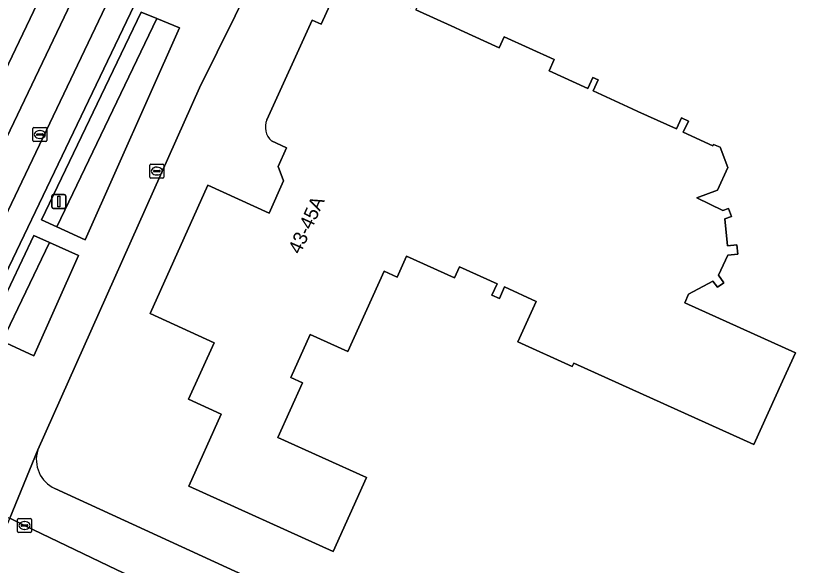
# Model space of a CAD drawing. Extents: x 161354 to 162026, y 386504 to 387460.
# Drawn here: x 161675.8 to 161732.9, y 386965.7 to 387005.2 of the extents above; entities that cross this region are included whole.
import ezdxf

# ---------------------------------------------------------------- set-up
doc = ezdxf.new("R2010")
doc.units = 0
for name, color, linetype in [('IMGEO_Brandkraan', 7, 'Continuous'), ('IMGEO_Erf', 7, 'Continuous'), ('IMGEO_Groenvoorziening', 7, 'Continuous'), ('IMGEO_Kolk', 7, 'Continuous'), ('IMGEO_Lichtmast', 7, 'Continuous'), ('IMGEO_Pand', 7, 'Continuous'), ('IMGEO_Pand_nummerreeks', 7, 'Continuous'), ('IMGEO_Parkeervlak_open', 7, 'Continuous'), ('IMGEO_Rijbaan_lokaal_open', 7, 'Continuous'), ('IMGEO_Voetpad_open', 7, 'Continuous')]:
    doc.layers.add(name, color=color, linetype=linetype)

msp = doc.modelspace()

# ---------------------------------------------------------------- linework, layer by layer
at = {"layer": 'IMGEO_Brandkraan'}
for p, q in [((161685.55, 386994.527), (161686.402, 386994.527)), ((161685.475, 386993.601), (161685.475, 386994.453)), ((161685.734, 386994.021), (161685.734, 386994.033)), ((161686.172, 386993.984), (161685.774, 386993.984)), ((161685.777, 386994.07), (161686.175, 386994.07)), ((161685.963, 386994.307), (161685.988, 386994.307)), ((161686.218, 386994.033), (161686.218, 386994.021)), ((161686.476, 386994.453), (161686.476, 386993.601)), ((161686.402, 386993.527), (161685.55, 386993.527)), ((161685.986, 386993.747), (161685.961, 386993.747))]:
    msp.add_line(p, q, dxfattribs=at)
for points in [[(161685.55, 386994.527), (161686.402, 386994.527)], [(161685.475, 386993.601), (161685.475, 386994.453)], [(161686.476, 386994.453), (161686.476, 386993.601)], [(161686.402, 386993.527), (161685.55, 386993.527)]]:
    msp.add_lwpolyline(points, dxfattribs=at)
for centre, radius, start, end in [((161685.552, 386994.451), 0.0765, 91.552, 178.448), ((161685.552, 386994.451), 0.0765, 91.552, 178.448), ((161686.4, 386994.451), 0.0765, 1.552, 88.448), ((161686.4, 386994.451), 0.0765, 1.552, 88.448), ((161685.774, 386994.03), 0.0403, 85.8775, 175.7526), ((161685.771, 386994.02), 0.0366, 178.938, 274.7102), ((161686.175, 386994.027), 0.043, 264.8664, 352.4533), ((161686.179, 386994.032), 0.0386, 1.7309, 96.639), ((161685.552, 386993.603), 0.0765, 181.552, 268.448), ((161685.552, 386993.603), 0.0765, 181.552, 268.448), ((161686.4, 386993.603), 0.0765, 271.552, 358.448), ((161686.4, 386993.603), 0.0765, 271.552, 358.448)]:
    msp.add_arc(centre, radius, start, end, dxfattribs=at)
for centre, major_axis, ratio, start_param, end_param in [((161685.962, 386994.027), (-0.387, 0.002), 0.722429, 4.712389, 7.853982), ((161685.987, 386994.027), (-0.39, 0.002), 0.717154, 1.570796, 4.712389)]:
    msp.add_ellipse(centre, major_axis=major_axis, ratio=ratio, start_param=start_param, end_param=end_param, dxfattribs=at)
at = {"layer": 'IMGEO_Erf'}
for points in [[(161713.413, 387041.445), (161703.036, 387025.535), (161695.643, 387012.888), (161692.864, 387007.756), (161689.028, 387000), (161677.419, 386973.992)], [(161693.871, 386997.706), (161697.124, 387004.878), (161697.77, 387004.592), (161699.187, 387007.684), (161698.908, 387008.484), (161699.315, 387008.627), (161699.631, 387007.85), (161701.853, 387006.834), (161702.257, 387006.651), (161704.191, 387005.781), (161704.552, 387006.583), (161704.935, 387006.41), (161704.575, 387005.61), (161707.395, 387004.33), (161707.791, 387004.15), (161710.572, 387002.888), (161710.942, 387003.671), (161714.518, 387002.039)], [(161714.518, 387002.039), (161714.153, 387001.239), (161716.943, 386999.959), (161717.31, 387000.759), (161717.692, 387000.584), (161717.325, 386999.784), (161720.131, 386998.51), (161720.534, 386998.312), (161723.313, 386997.053), (161723.683, 386997.846), (161724.168, 386997.624), (161723.803, 386996.826), (161725.917, 386995.851), (161725.967, 386995.944), (161726.453, 386995.738), (161727.001, 386994.284), (161726.263, 386992.654), (161724.78, 386992.095), (161726.64, 386991.204), (161727.045, 386991.336), (161727.256, 386990.775), (161726.797, 386990.602), (161726.988, 386988.665), (161727.656, 386988.731), (161727.723, 386988.055), (161727.002, 386987.99), (161726.335, 386986.54), (161726.716, 386986.009), (161726.259, 386985.681), (161725.937, 386986.129), (161724.185, 386985.181), (161723.907, 386984.566), (161731.86, 386980.966), (161730.94, 386978.934), (161728.878, 386974.379), (161715.94, 386980.234), (161715.829, 386979.99), (161711.923, 386981.758), (161713.24, 386984.668), (161710.956, 386985.702), (161710.585, 386984.883), (161710.055, 386985.124), (161710.417, 386985.924), (161707.73, 386987.14), (161707.372, 386986.348), (161703.921, 386987.91), (161703.239, 386986.403), (161702.304, 386986.826), (161699.693, 386981.057), (161696.993, 386982.279), (161695.594, 386979.189), (161696.432, 386978.81), (161694.658, 386974.89), (161701.031, 386972.006), (161698.631, 386966.703), (161688.264, 386971.395), (161690.605, 386976.567), (161688.246, 386977.635), (161690.086, 386981.701), (161685.488, 386983.788), (161689.639, 386993.011), (161694.038, 386991.005), (161695.084, 386993.316), (161694.688, 386994.367), (161695.294, 386995.706), (161694.209, 386996.197)], [(161678.646, 386971.221), (161703.934, 386959.616), (161710.18, 386956.726), (161717.11, 386954.446), (161724.516, 386952.463), (161732.347, 386950.52), (161737.556, 386949.582)]]:
    msp.add_lwpolyline(points, dxfattribs=at)
for centre, radius, start, end in [((161695.13, 386997.196), 1.358, 157.9336, 227.3169), ((161679.592, 386973.297), 2.281, 162.2597, 245.5079)]:
    msp.add_arc(centre, radius, start, end, dxfattribs=at)
at = {"layer": 'IMGEO_Groenvoorziening'}
for points in [[(161685.973, 387004.986), (161684.847, 387005.454), (161677.686, 386990.522), (161678.797, 386990.012)], [(161687.609, 387004.307), (161685.973, 387004.986), (161678.797, 386990.012), (161680.83, 386989.079)], [(161678.258, 386988.893), (161677.127, 386989.4), (161673.763, 386982.308), (161674.862, 386981.801)], [(161680.347, 386987.958), (161678.258, 386988.893), (161674.862, 386981.801), (161677.136, 386980.752)]]:
    msp.add_lwpolyline(points, close=True, dxfattribs=at)
at = {"layer": 'IMGEO_Kolk'}
for p, q in [((161677.067, 386996.226), (161677.067, 386997.078)), ((161677.142, 386997.152), (161677.994, 386997.152)), ((161677.555, 386996.932), (161677.58, 386996.932)), ((161678.068, 386997.078), (161678.068, 386996.226)), ((161677.326, 386996.646), (161677.326, 386996.658)), ((161677.764, 386996.609), (161677.366, 386996.609)), ((161677.369, 386996.695), (161677.767, 386996.695)), ((161677.578, 386996.372), (161677.553, 386996.372)), ((161677.81, 386996.658), (161677.81, 386996.646)), ((161677.994, 386996.152), (161677.142, 386996.152)), ((161675.966, 386968.145), (161675.966, 386968.997)), ((161676.041, 386969.071), (161676.893, 386969.071)), ((161676.454, 386968.851), (161676.479, 386968.851)), ((161676.967, 386968.997), (161676.967, 386968.145)), ((161676.225, 386968.565), (161676.225, 386968.577)), ((161676.663, 386968.528), (161676.265, 386968.528)), ((161676.268, 386968.614), (161676.666, 386968.614)), ((161676.477, 386968.291), (161676.452, 386968.291)), ((161676.709, 386968.577), (161676.709, 386968.565)), ((161676.893, 386968.071), (161676.041, 386968.071))]:
    msp.add_line(p, q, dxfattribs=at)
for points in [[(161677.067, 386996.226), (161677.067, 386997.078)], [(161677.142, 386997.152), (161677.994, 386997.152)], [(161678.068, 386997.078), (161678.068, 386996.226)], [(161677.994, 386996.152), (161677.142, 386996.152)], [(161675.966, 386968.145), (161675.966, 386968.997)], [(161676.041, 386969.071), (161676.893, 386969.071)], [(161676.967, 386968.997), (161676.967, 386968.145)], [(161676.893, 386968.071), (161676.041, 386968.071)]]:
    msp.add_lwpolyline(points, dxfattribs=at)
for centre, radius, start, end in [((161677.144, 386997.076), 0.0765, 91.552, 178.448), ((161677.144, 386997.076), 0.0765, 91.552, 178.448), ((161677.992, 386997.076), 0.0765, 1.552, 88.448), ((161677.992, 386997.076), 0.0765, 1.552, 88.448), ((161677.144, 386996.228), 0.0765, 181.552, 268.448), ((161677.144, 386996.228), 0.0765, 181.552, 268.448), ((161677.366, 386996.655), 0.0403, 85.8775, 175.7526), ((161677.363, 386996.645), 0.0366, 178.938, 274.7102), ((161677.767, 386996.652), 0.043, 264.8664, 352.4533), ((161677.771, 386996.657), 0.0386, 1.7309, 96.639), ((161677.992, 386996.228), 0.0765, 271.552, 358.448), ((161677.992, 386996.228), 0.0765, 271.552, 358.448), ((161676.043, 386968.995), 0.0765, 91.552, 178.448), ((161676.043, 386968.995), 0.0765, 91.552, 178.448), ((161676.891, 386968.995), 0.0765, 1.552, 88.448), ((161676.891, 386968.995), 0.0765, 1.552, 88.448), ((161676.265, 386968.574), 0.0403, 85.8775, 175.7526), ((161676.262, 386968.564), 0.0366, 178.938, 274.7102), ((161676.666, 386968.571), 0.043, 264.8664, 352.4533), ((161676.67, 386968.576), 0.0386, 1.7309, 96.639), ((161676.043, 386968.147), 0.0765, 181.552, 268.448), ((161676.043, 386968.147), 0.0765, 181.552, 268.448), ((161676.891, 386968.147), 0.0765, 271.552, 358.448), ((161676.891, 386968.147), 0.0765, 271.552, 358.448)]:
    msp.add_arc(centre, radius, start, end, dxfattribs=at)
for centre, major_axis, ratio, start_param, end_param in [((161677.554, 386996.652), (-0.387, 0.002), 0.722429, 4.712389, 7.853982), ((161677.579, 386996.652), (-0.39, 0.002), 0.717154, 1.570796, 4.712389), ((161676.453, 386968.571), (-0.387, 0.002), 0.722429, 4.712389, 7.853982), ((161676.478, 386968.571), (-0.39, 0.002), 0.717154, 1.570796, 4.712389)]:
    msp.add_ellipse(centre, major_axis=major_axis, ratio=ratio, start_param=start_param, end_param=end_param, dxfattribs=at)
at = {"layer": 'IMGEO_Lichtmast'}
for p, q in [((161678.433, 386991.441), (161678.433, 386992.241)), ((161678.433, 386992.241), (161678.433, 386991.441)), ((161678.533, 386992.341), (161679.323, 386992.341)), ((161679.323, 386992.341), (161678.533, 386992.341)), ((161679.423, 386992.241), (161679.423, 386991.441)), ((161679.423, 386991.441), (161679.423, 386992.241)), ((161679.323, 386991.341), (161678.533, 386991.341)), ((161678.533, 386991.341), (161679.323, 386991.341))]:
    msp.add_line(p, q, dxfattribs=at)
msp.add_lwpolyline([(161678.853, 386992.216), (161679.003, 386992.216), (161679.003, 386991.466), (161678.853, 386991.466), (161678.853, 386992.216)], dxfattribs=at)
for centre, start, end in [((161678.533, 386992.241), 90, 180), ((161678.533, 386992.241), 90, 180), ((161679.323, 386992.241), 0, 90), ((161679.323, 386992.241), 360, 90), ((161678.533, 386991.441), 180, 270), ((161678.533, 386991.441), 180, 270), ((161679.323, 386991.441), 270, 0), ((161679.323, 386991.441), 270, 0)]:
    msp.add_arc(centre, 0.1, start, end, dxfattribs=at)
at = {"layer": 'IMGEO_Pand'}
for points in [[(161699.187, 387007.684), (161697.77, 387004.592), (161697.124, 387004.878), (161693.871, 386997.706)], [(161724.78, 386992.095), (161726.263, 386992.654), (161727.001, 386994.284), (161726.453, 386995.738), (161725.967, 386995.944), (161725.917, 386995.851), (161723.803, 386996.826), (161724.168, 386997.624), (161723.683, 386997.846), (161723.313, 386997.053), (161720.534, 386998.312), (161720.131, 386998.51), (161717.325, 386999.784), (161717.692, 387000.584), (161717.31, 387000.759), (161716.943, 386999.959), (161714.153, 387001.239), (161714.518, 387002.039), (161710.942, 387003.671), (161710.572, 387002.888), (161707.791, 387004.15), (161707.395, 387004.33), (161704.575, 387005.61)], [(161694.209, 386996.197), (161695.294, 386995.706), (161694.688, 386994.367), (161695.084, 386993.316), (161694.038, 386991.005), (161689.639, 386993.011), (161685.488, 386983.788), (161690.086, 386981.701), (161688.246, 386977.635), (161690.605, 386976.567), (161688.264, 386971.395), (161698.631, 386966.703), (161701.031, 386972.006), (161694.658, 386974.89), (161696.432, 386978.81), (161695.594, 386979.189), (161696.993, 386982.279), (161699.693, 386981.057), (161702.304, 386986.826), (161703.239, 386986.403), (161703.921, 386987.91), (161707.372, 386986.348), (161707.73, 386987.14), (161710.417, 386985.924), (161710.055, 386985.124), (161710.585, 386984.883), (161710.956, 386985.702), (161713.24, 386984.668), (161711.923, 386981.758), (161715.829, 386979.99), (161715.94, 386980.234), (161728.878, 386974.379), (161730.94, 386978.934), (161731.86, 386980.966), (161723.907, 386984.566), (161724.185, 386985.181), (161725.937, 386986.129), (161726.259, 386985.681), (161726.716, 386986.009), (161726.335, 386986.54), (161727.002, 386987.99), (161727.723, 386988.055), (161727.656, 386988.731), (161726.988, 386988.665), (161726.797, 386990.602), (161727.256, 386990.775), (161727.045, 386991.336), (161726.64, 386991.204), (161724.78, 386992.095)]]:
    msp.add_lwpolyline(points, dxfattribs=at)
msp.add_arc((161695.13, 386997.196), 1.358, 157.9336, 227.3169, dxfattribs=at)
at = {"layer": 'IMGEO_Parkeervlak_open'}
msp.add_lwpolyline([(161686.779, 387015.299), (161671.511, 386983.329), (161673.133, 386982.564), (161688.427, 387014.484)], close=True, dxfattribs=at)
at = {"layer": 'IMGEO_Rijbaan_lokaal_open'}
for points in [[(161682.437, 387021.149), (161681.983, 387021.329), (161681.574, 387020.458), (161683.75, 387019.375), (161683.561, 387018.983), (161680.977, 387013.629), (161664.695, 386979.587), (161666.643, 386978.635), (161685.481, 387018.029), (161686.934, 387021.178)], [(161686.934, 387021.178), (161685.481, 387018.029), (161666.643, 386978.635), (161668.836, 386977.492)], [(161668.89, 386977.819), (161671.511, 386983.329), (161686.779, 387015.299)], [(161702.406, 386956.407), (161699.061, 386957.966), (161683.099, 386965.38), (161676.467, 386968.571), (161675.409, 386969.085), (161673.318, 386964.474), (161675.946, 386963.269)]]:
    msp.add_lwpolyline(points, dxfattribs=at)
msp.add_lwpolyline([(161680.977, 387013.629), (161683.561, 387018.983), (161683.75, 387019.375), (161681.574, 387020.458), (161677.895, 387012.773), (161675.699, 387008.193), (161672.284, 387001.058), (161667.967, 386992.057), (161664.397, 386984.566), (161659.348, 386974.057), (161659.764, 386973.893), (161657.878, 386969.873), (161656.852, 386967.721), (161658.609, 386966.862), (161664.695, 386979.587)], close=True, dxfattribs=at)
at = {"layer": 'IMGEO_Voetpad_open'}
for points in [[(161670.245, 386972.344), (161671.176, 386971.663), (161672.256, 386971.1), (161674.68, 386969.96), (161674.495, 386969.525), (161675.367, 386969.105), (161675.409, 386969.085), (161677.419, 386973.992), (161689.028, 387000), (161692.864, 387007.756), (161695.643, 387012.888), (161703.036, 387025.535), (161713.413, 387041.445)], [(161688.332, 387018.449), (161687.597, 387016.959), (161686.779, 387015.299), (161688.427, 387014.484), (161673.133, 386982.564), (161671.511, 386983.329), (161668.89, 386977.819)], [(161677.419, 386973.992), (161675.409, 386969.085), (161676.467, 386968.571), (161683.099, 386965.38), (161699.061, 386957.966), (161699.268, 386958.42), (161702.613, 386956.861), (161702.406, 386956.407)], [(161756.72, 386947.593), (161748.381, 386948.463), (161746.595, 386948.672), (161739.488, 386949.384), (161737.556, 386949.582), (161732.347, 386950.52), (161724.516, 386952.463), (161717.11, 386954.446), (161710.18, 386956.726), (161703.934, 386959.616), (161678.646, 386971.221)]]:
    msp.add_lwpolyline(points, dxfattribs=at)
for points in [[(161687.609, 387004.307), (161680.83, 386989.079), (161678.797, 386990.012), (161677.686, 386990.522), (161684.847, 387005.454), (161685.973, 387004.986)], [(161680.347, 386987.958), (161677.136, 386980.752), (161674.862, 386981.801), (161673.763, 386982.308), (161677.127, 386989.4), (161678.258, 386988.893)]]:
    msp.add_lwpolyline(points, close=True, dxfattribs=at)
msp.add_arc((161679.592, 386973.297), 2.281, 162.2597, 245.5079, dxfattribs=at)

# ---------------------------------------------------------------- texts
at = {"layer": 'IMGEO_Pand_nummerreeks'}
msp.add_text('43-45A', height=1, rotation=65.6495, dxfattribs=at).set_placement((161696.277, 386987.998))

doc.saveas('drawing.dxf')
